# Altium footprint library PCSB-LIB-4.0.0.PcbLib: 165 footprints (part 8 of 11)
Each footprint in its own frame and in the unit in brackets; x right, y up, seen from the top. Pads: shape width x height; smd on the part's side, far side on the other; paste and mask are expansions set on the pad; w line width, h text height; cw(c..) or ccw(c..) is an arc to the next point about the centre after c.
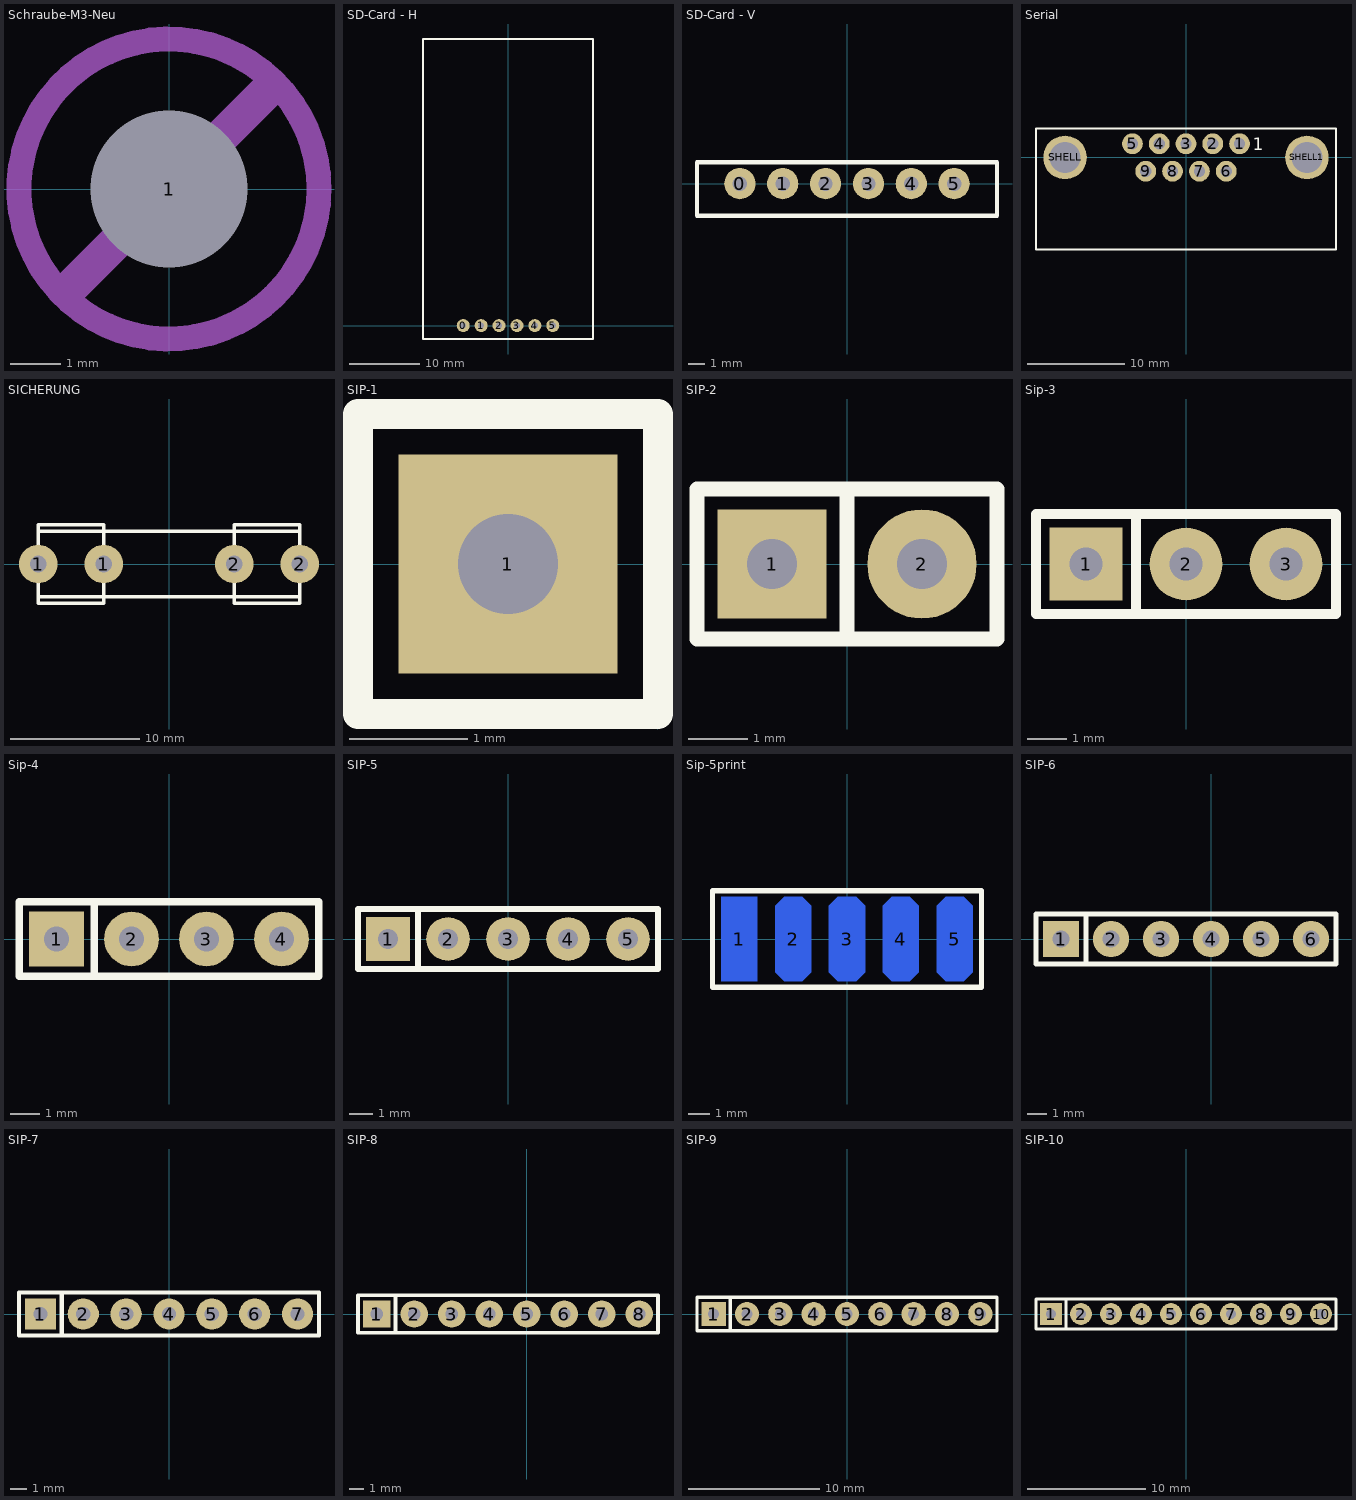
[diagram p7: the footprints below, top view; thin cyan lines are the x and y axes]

## Schraube-M3-Neu [mm] "Befestigungsschraube für Prints"
pads (1):
  round 0.75 hole 3.15 unplated: 1(0,0)
Mechanical 1:
  circle w0.5: c0,0 r3
  lines w0.7: -2,-2 2,2

## SD-Card - H [mm]
pads (6):
  round 1.85 hole 0.85: 0(-6.35,0) 1(-3.81,0) 2(-1.27,0) 3(1.27,0) 4(3.81,0) 5(6.35,0)
Top Overlay:
  lines w0.254: -12.065,-1.905 -12.065,40.64 12.065,40.64 12.065,-1.905 -12.065,-1.905

## SD-Card - V [mm]
pads (6):
  round 1.85 hole 0.85: 0(-6.35,0) 1(-3.81,0) 2(-1.27,0) 3(1.27,0) 4(3.81,0) 5(6.35,0)
Top Overlay:
  lines w0.254: -8.89,-1.905 -8.89,1.27 8.89,1.27 8.89,-1.905 -8.89,-1.905

## Serial [mm]
pads (11):
  round 2.15 hole 1.15: 1(5.54,1.42) 2(2.77,1.42) 3(0,1.42) 4(-2.77,1.42) 5(-5.54,1.42) 6(4.155,-1.42) 7(1.385,-1.42) 8(-1.385,-1.42) 9(-4.155,-1.42)
  round 4.5 hole 3.2: SHELL(-12.5,0) SHELL1(12.5,0)
Top Overlay:
  lines w0.2: -15.5,-9.52 -15.5,3 15.5,3 15.5,-9.52 -15.5,-9.52
  text "1" at 6.915,0.735 h1.27
Mechanical 13:
  text "1" at 6.915,0.735 h1.27

## SICHERUNG [mm]
pads (4):
  round 3 hole 1.3: 1(-10.163,0.008) 1(-5.083,0.008) 2(5.077,0.008) 2(10.157,0.008)
Top Overlay:
  lines w0.254: -10.163,-2.532 -10.163,2.548 ; -10.163,-2.532 10.157,-2.532 ; -10.163,-2.532 -10.163,-3.04 -5.083,-3.04 -5.083,-2.532 -5.083,2.548 -5.083,3.056 -10.163,3.056 -10.163,2.548 ; -10.163,2.548 10.157,2.548 ; 10.157,-2.532 10.157,2.548 ; 10.157,-2.532 10.157,-3.04 5.077,-3.04 5.077,-2.532 5.077,2.548 5.077,3.056 10.157,3.056 10.157,2.548

## SIP-1 [mm]
pads (1):
  rect 1.85x1.85 hole 0.85: 1(-1.27,0)
Top Overlay:
  lines w0.254: -2.54,-1.27 0,-1.27 0,1.27 -2.54,1.27 -2.54,-1.27

## SIP-2 [mm]
pads (2):
  rect 1.85x1.85 hole 0.85: 1(-1.27,0)
  round 1.85 hole 0.85: 2(1.27,0)
Top Overlay:
  lines w0.254: 0,-1.27 0,1.27 ; -2.54,-1.27 2.54,-1.27 2.54,1.27 -2.54,1.27 -2.54,-1.27

## Sip-3 [mm]
pads (3):
  rect 1.85x1.85 hole 0.85: 1(-2.54,0)
  round 1.85 hole 0.85: 2(0,0) 3(2.54,0)
Top Overlay:
  lines w0.254: -1.27,-1.27 -1.27,1.27 ; -3.81,-1.27 3.81,-1.27 3.81,1.27 -3.81,1.27 -3.81,-1.27

## Sip-4 [mm]
pads (4):
  rect 1.85x1.85 hole 0.85: 1(-3.81,0)
  round 1.85 hole 0.85: 2(-1.27,0) 3(1.27,0) 4(3.81,0)
Top Overlay:
  lines w0.254: -2.54,-1.27 -2.54,1.27 ; -5.08,-1.27 5.08,-1.27 5.08,1.27 -5.08,1.27 -5.08,-1.27

## SIP-5 [mm]
pads (5):
  rect 1.85x1.85 hole 0.85: 1(-5.08,0)
  round 1.85 hole 0.85: 2(-2.54,0) 3(0,0) 4(2.54,0) 5(5.08,0)
Top Overlay:
  lines w0.254: -3.81,-1.27 -3.81,1.27 ; -6.35,-1.27 6.35,-1.27 6.35,1.27 -6.35,1.27 -6.35,-1.27

## Sip-5print [mm]
pads (5):
  rect 1.7x4 smd far side: 1(-5.08,0)
  oct 1.7x4 smd far side: 2(-2.54,0) 3(0,0) 4(2.54,0) 5(5.08,0)
Top Overlay:
  lines w0.254: -6.35,-2.286 6.35,-2.286 6.35,2.286 -6.35,2.286 -6.35,-2.286

## SIP-6 [mm]
pads (6):
  rect 1.85x1.85 hole 0.85: 1(-7.62,0)
  round 1.85 hole 0.85: 2(-5.08,0) 3(-2.54,0) 4(0,0) 5(2.54,0) 6(5.08,0)
Top Overlay:
  lines w0.254: -6.35,-1.27 -6.35,1.27 ; -8.89,-1.27 6.35,-1.27 6.35,1.27 -8.89,1.27 -8.89,-1.27

## SIP-7 [mm]
pads (7):
  rect 1.85x1.85 hole 0.85: 1(-7.62,0)
  round 1.85 hole 0.85: 2(-5.08,0) 3(-2.54,0) 4(0,0) 5(2.54,0) 6(5.08,0) 7(7.62,0)
Top Overlay:
  lines w0.254: -6.35,-1.27 -6.35,1.27 ; -8.89,-1.27 8.89,-1.27 8.89,1.27 -8.89,1.27 -8.89,-1.27

## SIP-8 [mm]
pads (8):
  rect 1.85x1.85 hole 0.85: 1(-10.16,0)
  round 1.85 hole 0.85: 2(-7.62,0) 3(-5.08,0) 4(-2.54,0) 5(0,0) 6(2.54,0) 7(5.08,0) 8(7.62,0)
Top Overlay:
  lines w0.254: -8.89,-1.27 -8.89,1.27 ; -11.43,-1.27 -11.43,1.27 8.89,1.27 8.89,-1.27 -11.43,-1.27

## SIP-9 [mm]
pads (9):
  rect 1.85x1.85 hole 0.85: 1(-10.16,0)
  round 1.85 hole 0.85: 2(-7.62,0) 3(-5.08,0) 4(-2.54,0) 5(0,0) 6(2.54,0) 7(5.08,0) 8(7.62,0) 9(10.16,0)
Top Overlay:
  lines w0.254: -8.89,-1.27 -8.89,1.27 ; -11.43,-1.27 11.43,-1.27 11.43,1.27 -11.43,1.27 -11.43,-1.27

## SIP-10 [mm]
pads (10):
  rect 1.85x1.85 hole 0.85: 1(-11.43,0)
  round 1.85 hole 0.85: 2(-8.89,0) 3(-6.35,0) 4(-3.81,0) 5(-1.27,0) 6(1.27,0) 7(3.81,0) 8(6.35,0) 9(8.89,0) 10(11.43,0)
Top Overlay:
  lines w0.254: -10.16,-1.27 -10.16,1.27 ; -12.7,-1.27 12.7,-1.27 12.7,1.27 -12.7,1.27 -12.7,-1.27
